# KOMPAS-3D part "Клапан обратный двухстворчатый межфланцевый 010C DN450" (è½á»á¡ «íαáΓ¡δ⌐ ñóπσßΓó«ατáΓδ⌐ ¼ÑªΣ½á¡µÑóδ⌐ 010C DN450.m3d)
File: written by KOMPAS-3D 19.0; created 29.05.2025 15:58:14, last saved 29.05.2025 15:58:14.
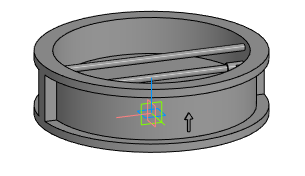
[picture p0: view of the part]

Document properties: Полное имя файла: E:\Dendor Работа Сачек\3D для проекитирвщиков\5.2 Тип 010C, 010C.Y Клапан обратный двухстворчатый межфланцевый\stp_Клапан обратный двухстворчатый межфланцевый 010C\Клапан обратный двухстворчатый межфланцевый 010C DN450.m3d

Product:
- Part/product: Клапан обратный двухстворчатый межфланцевый 010C DN450

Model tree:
1. Операция без истории:1  (labels: Клапан обратный двухстворчатый межфланцевый 010C DN450)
